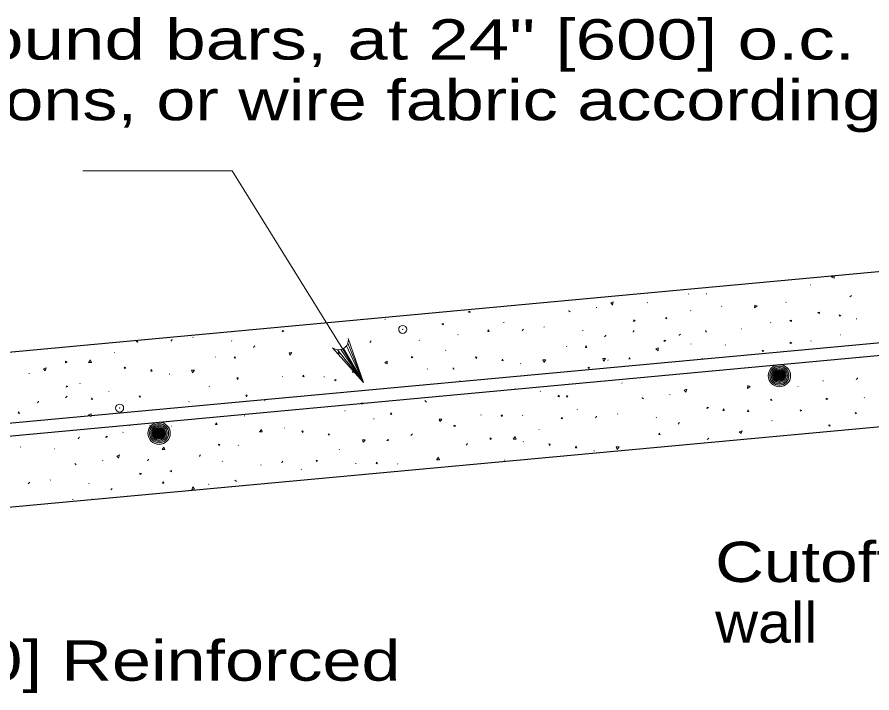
# Model space of a CAD drawing. Extents: x 1083.1 to 1117.1, y 697.4 to 741.4.
# Drawn here: x 1105.172 to 1108.478, y 723.186 to 725.801 of the extents above; entities that cross this region are included whole.
import ezdxf

# ---------------------------------------------------------------- set-up
doc = ezdxf.new("R2010")
doc.units = 0
doc.header["$LTSCALE"] = 0.062
doc.header["$PDMODE"] = 32
doc.header["$PDSIZE"] = 0.031
doc.layers.add('1', color=7, linetype='Continuous', lineweight=13)

msp = doc.modelspace()

# ---------------------------------------------------------------- hatches: boundary and pattern name
at = {"layer": '1'}
h = msp.add_hatch(color=256, dxfattribs=at)
edge = h.paths.add_edge_path()
edge.add_ellipse((1108.12022, 724.41349), major_axis=(0.04324, 0), ratio=0.9998948, start_angle=0, end_angle=360)
h = msp.add_hatch(color=256, dxfattribs=at)
edge = h.paths.add_edge_path()
edge.add_ellipse((1108.12004, 724.41361), major_axis=(0.03676, 0), ratio=0.9998948, start_angle=0, end_angle=360)
h = msp.add_hatch(color=256, dxfattribs=at)
edge = h.paths.add_edge_path()
edge.add_ellipse((1108.11984, 724.41371), major_axis=(0.03124, 0), ratio=0.9998948, start_angle=0, end_angle=360)
h = msp.add_hatch(color=256, dxfattribs=at)
edge = h.paths.add_edge_path()
edge.add_ellipse((1108.11972, 724.4138), major_axis=(0.02656, 0), ratio=0.9998948, start_angle=0, end_angle=360)
h = msp.add_hatch(color=256, dxfattribs=at)
edge = h.paths.add_edge_path()
edge.add_ellipse((1108.11957, 724.41387), major_axis=(0.02257, 0), ratio=0.9998948, start_angle=0, end_angle=360)
h = msp.add_hatch(color=256, dxfattribs=at)
edge = h.paths.add_edge_path()
edge.add_ellipse((1108.11941, 724.41393), major_axis=(0.01919, 0), ratio=0.9998948, start_angle=0, end_angle=360)
h = msp.add_hatch(color=256, dxfattribs=at)
edge = h.paths.add_edge_path()
edge.add_ellipse((1108.11928, 724.41399), major_axis=(0.01631, 0), ratio=0.9998948, start_angle=0, end_angle=360)
h = msp.add_hatch(color=256, dxfattribs=at)
edge = h.paths.add_edge_path()
edge.add_ellipse((1108.11912, 724.41403), major_axis=(0.01386, 0), ratio=0.9998948, start_angle=0, end_angle=360)
h = msp.add_hatch(color=256, dxfattribs=at)
edge = h.paths.add_edge_path()
edge.add_ellipse((1108.11898, 724.41407), major_axis=(0.01178, 0), ratio=0.9998948, start_angle=0, end_angle=360)
h = msp.add_hatch(color=256, dxfattribs=at)
edge = h.paths.add_edge_path()
edge.add_ellipse((1108.11882, 724.4141), major_axis=(0.01002, 0), ratio=0.9998948, start_angle=0, end_angle=360)
h = msp.add_hatch(color=256, dxfattribs=at)
edge = h.paths.add_edge_path()
edge.add_ellipse((1108.11869, 724.41413), major_axis=(0.00851, 0), ratio=0.9998948, start_angle=0, end_angle=360)
h = msp.add_hatch(color=256, dxfattribs=at)
edge = h.paths.add_edge_path()
edge.add_ellipse((1108.11857, 724.4142), major_axis=(0.00724, 0), ratio=0.9998948, start_angle=0, end_angle=360)
h = msp.add_hatch(color=256, dxfattribs=at)
edge = h.paths.add_edge_path()
edge.add_ellipse((1108.11847, 724.41426), major_axis=(0.00615, 0), ratio=0.9998948, start_angle=0, end_angle=360)
h = msp.add_hatch(color=256, dxfattribs=at)
edge = h.paths.add_edge_path()
edge.add_ellipse((1108.11835, 724.41431), major_axis=(0.00523, 0), ratio=0.9998948, start_angle=0, end_angle=360)
h = msp.add_hatch(color=256, dxfattribs=at)
edge = h.paths.add_edge_path()
edge.add_ellipse((1108.11824, 724.41435), major_axis=(0.00444, 0), ratio=0.9998948, start_angle=0, end_angle=360)
h = msp.add_hatch(color=256, dxfattribs=at)
edge = h.paths.add_edge_path()
edge.add_ellipse((1108.11835, 724.41434), major_axis=(0.00378, 0), ratio=0.9998948, start_angle=0, end_angle=360)
h = msp.add_hatch(color=256, dxfattribs=at)
edge = h.paths.add_edge_path()
edge.add_ellipse((1108.11845, 724.41433), major_axis=(0.00321, 0), ratio=0.9998948, start_angle=0, end_angle=360)
h = msp.add_hatch(color=256, dxfattribs=at)
edge = h.paths.add_edge_path()
edge.add_ellipse((1108.11854, 724.41433), major_axis=(0.00273, 0), ratio=0.9998948, start_angle=0, end_angle=360)
h = msp.add_hatch(color=256, dxfattribs=at)
edge = h.paths.add_edge_path()
edge.add_ellipse((1108.11857, 724.41432), major_axis=(0.00232, 0), ratio=0.9998948, start_angle=0, end_angle=360)
h = msp.add_hatch(color=256, dxfattribs=at)
edge = h.paths.add_edge_path()
edge.add_ellipse((1108.11856, 724.41436), major_axis=(0.00197, 0), ratio=0.9998948, start_angle=0, end_angle=360)
h = msp.add_hatch(color=256, dxfattribs=at)
edge = h.paths.add_edge_path()
edge.add_ellipse((1108.11872, 724.41435), major_axis=(0.00168, 0), ratio=0.9998948, start_angle=0, end_angle=360)
h = msp.add_hatch(color=256, dxfattribs=at)
edge = h.paths.add_edge_path()
edge.add_ellipse((1105.72135, 724.19072), major_axis=(0.04324, 0), ratio=0.9998948, start_angle=0, end_angle=360)
h = msp.add_hatch(color=256, dxfattribs=at)
edge = h.paths.add_edge_path()
edge.add_ellipse((1105.72121, 724.19093), major_axis=(0.03676, 0), ratio=0.9998948, start_angle=0, end_angle=360)
h = msp.add_hatch(color=256, dxfattribs=at)
edge = h.paths.add_edge_path()
edge.add_ellipse((1105.7211, 724.19111), major_axis=(0.03124, 0), ratio=0.9998948, start_angle=0, end_angle=360)
h = msp.add_hatch(color=256, dxfattribs=at)
edge = h.paths.add_edge_path()
edge.add_ellipse((1105.721, 724.19126), major_axis=(0.02656, 0), ratio=0.9998948, start_angle=0, end_angle=360)
h = msp.add_hatch(color=256, dxfattribs=at)
edge = h.paths.add_edge_path()
edge.add_ellipse((1105.72092, 724.19139), major_axis=(0.02257, 0), ratio=0.9998948, start_angle=0, end_angle=360)
h = msp.add_hatch(color=256, dxfattribs=at)
edge = h.paths.add_edge_path()
edge.add_ellipse((1105.72085, 724.1915), major_axis=(0.01919, 0), ratio=0.9998948, start_angle=0, end_angle=360)
h = msp.add_hatch(color=256, dxfattribs=at)
edge = h.paths.add_edge_path()
edge.add_ellipse((1105.72079, 724.19159), major_axis=(0.01631, 0), ratio=0.9998948, start_angle=0, end_angle=360)
h = msp.add_hatch(color=256, dxfattribs=at)
edge = h.paths.add_edge_path()
edge.add_ellipse((1105.72074, 724.19167), major_axis=(0.01386, 0), ratio=0.9998948, start_angle=0, end_angle=360)
h = msp.add_hatch(color=256, dxfattribs=at)
edge = h.paths.add_edge_path()
edge.add_ellipse((1105.72069, 724.19173), major_axis=(0.01178, 0), ratio=0.9998948, start_angle=0, end_angle=360)
h = msp.add_hatch(color=256, dxfattribs=at)
edge = h.paths.add_edge_path()
edge.add_ellipse((1105.72066, 724.19179), major_axis=(0.01002, 0), ratio=0.9998948, start_angle=0, end_angle=360)
h = msp.add_hatch(color=256, dxfattribs=at)
edge = h.paths.add_edge_path()
edge.add_ellipse((1105.72062, 724.19184), major_axis=(0.00851, 0), ratio=0.9998948, start_angle=0, end_angle=360)
h = msp.add_hatch(color=256, dxfattribs=at)
edge = h.paths.add_edge_path()
edge.add_ellipse((1105.7206, 724.19188), major_axis=(0.00724, 0), ratio=0.9998948, start_angle=0, end_angle=360)
h = msp.add_hatch(color=256, dxfattribs=at)
edge = h.paths.add_edge_path()
edge.add_ellipse((1105.72058, 724.19192), major_axis=(0.00615, 0), ratio=0.9998948, start_angle=0, end_angle=360)
h = msp.add_hatch(color=256, dxfattribs=at)
edge = h.paths.add_edge_path()
edge.add_ellipse((1105.72056, 724.19195), major_axis=(0.00523, 0), ratio=0.9998948, start_angle=0, end_angle=360)
h = msp.add_hatch(color=256, dxfattribs=at)
edge = h.paths.add_edge_path()
edge.add_ellipse((1105.72054, 724.19197), major_axis=(0.00444, 0), ratio=0.9998948, start_angle=0, end_angle=360)
h = msp.add_hatch(color=256, dxfattribs=at)
edge = h.paths.add_edge_path()
edge.add_ellipse((1105.72053, 724.19199), major_axis=(0.00378, 0), ratio=0.9998948, start_angle=0, end_angle=360)
h = msp.add_hatch(color=256, dxfattribs=at)
edge = h.paths.add_edge_path()
edge.add_ellipse((1105.72051, 724.19201), major_axis=(0.00321, 0), ratio=0.9998948, start_angle=0, end_angle=360)

# ---------------------------------------------------------------- linework, layer by layer
for p, q in [((1105.42633, 725.20642), (1106.00458, 725.20642)), ((1106.51225, 724.38708), (1106.00458, 725.20642)), ((1108.32183, 724.79408), (1108.32808, 724.79883)), ((1108.241, 724.7655), (1108.239, 724.76475)), ((1107.76858, 724.72933), (1107.77058, 724.73)), ((1107.83717, 724.7295), (1107.83917, 724.73017)), ((1107.60925, 724.69483), (1107.61008, 724.69675)), ((1108.14667, 724.69775), (1108.1455, 724.69617)), ((1107.41175, 724.67742), (1107.41375, 724.67675)), ((1107.7775, 724.66392), (1107.77675, 724.66592)), ((1107.898, 724.68267), (1107.89683, 724.68117)), ((1106.595, 724.631), (1106.597, 724.63175)), ((1108.41917, 724.63408), (1108.41717, 724.63333)), ((1107.05375, 724.61867), (1107.05525, 724.61983)), ((1107.20992, 724.6015), (1107.21142, 724.60267)), ((1107.97225, 724.59442), (1107.97425, 724.59508)), ((1108.08575, 724.618), (1108.08775, 724.61867)), ((1105.85167, 724.56108), (1105.85317, 724.56233)), ((1106.8785, 724.57292), (1106.8765, 724.57217)), ((1107.36058, 724.58958), (1107.35975, 724.58758)), ((1108.35683, 724.57183), (1108.35492, 724.571)), ((1106.00233, 724.54925), (1106.0015, 724.54725)), ((1106.44558, 724.52883), (1106.51225, 724.38708)), ((1106.45142, 724.53942), (1106.51225, 724.38708)), ((1106.72717, 724.55025), (1106.72908, 724.551)), ((1107.29817, 724.52725), (1107.2975, 724.52533)), ((1107.77867, 724.53492), (1107.7795, 724.53692)), ((1107.90992, 724.532), (1107.91192, 724.53283)), ((1108.24333, 724.54825), (1108.24133, 724.54742)), ((1105.54933, 724.50333), (1105.54867, 724.50133)), ((1106.41167, 724.51383), (1106.51225, 724.38708)), ((1106.424, 724.51475), (1106.51225, 724.38708)), ((1106.43458, 724.51908), (1106.51225, 724.38708)), ((1106.8305, 724.51192), (1106.82933, 724.51042)), ((1105.93992, 724.48683), (1105.93925, 724.48483)), ((1107.12017, 724.46067), (1107.11942, 724.45875)), ((1107.45767, 724.47475), (1107.45683, 724.47283)), ((1107.82208, 724.48083), (1107.82283, 724.47883)), ((1108.43108, 724.48342), (1108.43225, 724.48492)), ((1106.75775, 724.439), (1106.75967, 724.43967)), ((1105.21808, 724.4225), (1105.22008, 724.42175)), ((1105.76192, 724.42025), (1105.76117, 724.41825)), ((1106.19892, 724.41208), (1106.19825, 724.41008)), ((1106.36025, 724.41025), (1106.35958, 724.40825)), ((1106.88492, 724.39242), (1106.88567, 724.39442)), ((1107.44725, 724.39392), (1107.4465, 724.39192)), ((1108.29025, 724.39383), (1108.28833, 724.393)), ((1105.41542, 724.38258), (1105.41617, 724.38458)), ((1105.91633, 724.37333), (1105.91567, 724.37142)), ((1107.0985, 724.36342), (1107.09767, 724.36142)), ((1107.5125, 724.385), (1107.5105, 724.38567)), ((1108.193, 724.372), (1108.191, 724.37133)), ((1105.52675, 724.352), (1105.52742, 724.35392)), ((1106.39892, 724.34192), (1106.39883, 724.34192)), ((1106.92708, 724.32875), (1106.92717, 724.32867)), ((1107.19483, 724.35283), (1107.19642, 724.354)), ((1107.69575, 724.34042), (1107.69775, 724.33967)), ((1108.44825, 724.32725), (1108.4495, 724.32883)), ((1105.83667, 724.31242), (1105.83817, 724.31367)), ((1106.13117, 724.31783), (1106.12958, 724.31667)), ((1106.44108, 724.27825), (1106.44033, 724.27625)), ((1106.96575, 724.26042), (1106.9665, 724.26242)), ((1107.12708, 724.25858), (1107.12792, 724.26058)), ((1107.33758, 724.28167), (1107.33908, 724.28283)), ((1107.49383, 724.2645), (1107.49533, 724.26567)), ((1106.05142, 724.25692), (1106.05208, 724.25892)), ((1106.55233, 724.24758), (1106.55167, 724.24567)), ((1107.64442, 724.25258), (1107.64375, 724.25058)), ((1108.08992, 724.23925), (1108.09192, 724.24008)), ((1105.58233, 724.19525), (1105.58075, 724.194)), ((1105.6075, 724.21992), (1105.60817, 724.22192)), ((1105.76883, 724.21817), (1105.76967, 724.22017)), ((1106.20583, 724.20992), (1106.20658, 724.21192)), ((1107.19158, 724.20683), (1107.19075, 724.20483)), ((1108.15833, 724.20075), (1108.15817, 724.20075)), ((1105.18492, 724.13883), (1105.18408, 724.13683)), ((1105.31883, 724.13008), (1105.31683, 724.13075)), ((1106.02783, 724.14333), (1106.02858, 724.14533)), ((1106.41842, 724.12683), (1106.41908, 724.12883)), ((1107.13058, 724.15883), (1107.12908, 724.15767)), ((1107.40408, 724.12367), (1107.40333, 724.12175)), ((1105.50208, 724.0855), (1105.50392, 724.08467)), ((1105.9655, 724.08108), (1105.96625, 724.08308)), ((1106.11608, 724.06908), (1106.11467, 724.068)), ((1106.48275, 724.075), (1106.48208, 724.07308)), ((1106.64425, 724.07325), (1106.64342, 724.07125)), ((1107.0575, 724.08608), (1107.05833, 724.088)), ((1106.27225, 724.05192), (1106.27075, 724.05083)), ((1105.30017, 724.0095), (1105.30167, 724.01075)), ((1105.45075, 723.99758), (1105.45, 723.99567)), ((1105.91425, 723.99325), (1105.91225, 723.99392)), ((1105.38842, 723.93525), (1105.38767, 723.93333)), ((1105.46217, 723.93675), (1105.461, 723.93333)), ((1105.46383, 723.93367), (1105.46217, 723.93675))]:
    msp.add_line(p, q, dxfattribs=at)
at = {"layer": '1', "lineweight": 25}
for p, q in [((1110.5145, 724.72675), (1103.31092, 724.05875)), ((1110.51908, 724.67717), (1103.29317, 724.007)), ((1110.14883, 724.368), (1103.29017, 723.73208))]:
    msp.add_line(p, q, dxfattribs=at)
msp.add_lwpolyline([(1110.14883, 724.96767), (1107.49917, 724.722), (1103.29017, 724.33175)], dxfattribs=at)
at = {"layer": '1'}
for points in [[(1108.33158, 724.79917), (1108.33142, 724.79058), (1108.322, 724.794)], [(1108.3985, 724.7235), (1108.39792, 724.72208), (1108.393, 724.71792)], [(1107.4745, 724.68692), (1107.478, 724.69875), (1107.46783, 724.69483), (1107.47433, 724.68717)], [(1107.3055, 724.66625), (1107.30608, 724.66483), (1107.31108, 724.66067)], [(1108.0345, 724.68342), (1108.02458, 724.676), (1108.02475, 724.68692), (1108.03425, 724.6835)], [(1107.131, 724.59308), (1107.12958, 724.5925), (1107.12542, 724.5875)], [(1107.44992, 724.56892), (1107.4485, 724.56833), (1107.44442, 724.56342)], [(1107.5535, 724.583), (1107.55475, 724.58358), (1107.559, 724.58858)], [(1107.73233, 724.569), (1107.73292, 724.57042), (1107.73792, 724.57458)], [(1107.83325, 724.58708), (1107.83467, 724.5865), (1107.83883, 724.5815)], [(1105.63575, 724.54925), (1105.63408, 724.54442), (1105.63942, 724.54358), (1105.6365, 724.54933)], [(1105.77275, 724.55258), (1105.77133, 724.552), (1105.76708, 724.547)], [(1106.09167, 724.5285), (1106.09033, 724.52792), (1106.08617, 724.52292)], [(1106.453, 724.55758), (1106.51225, 724.38708), (1106.392, 724.52167)], [(1106.5365, 724.54233), (1106.53708, 724.54375), (1106.54208, 724.54792)], [(1105.23158, 724.51175), (1105.23158, 724.51167), (1105.23192, 724.51175)], [(1106.2275, 724.49283), (1106.23492, 724.50267), (1106.224, 724.5025), (1106.22742, 724.49308)], [(1107.64225, 724.51742), (1107.652, 724.51), (1107.65192, 724.52092), (1107.64242, 724.5175)], [(1105.45633, 724.47433), (1105.449, 724.46458), (1105.45983, 724.46475), (1105.4565, 724.47417)], [(1106.59417, 724.46283), (1106.604, 724.47025), (1106.60383, 724.45925), (1106.59433, 724.46275)], [(1107.20917, 724.46517), (1107.21658, 724.47492), (1107.20567, 724.47475), (1107.20908, 724.46533)], [(1107.44067, 724.46992), (1107.448, 724.47975), (1107.437, 724.47958), (1107.4405, 724.47008)], [(1105.28075, 724.432), (1105.28433, 724.44375), (1105.27417, 724.43983), (1105.28067, 724.43217)], [(1105.85092, 724.42467), (1105.85842, 724.4345), (1105.84742, 724.43442), (1105.85075, 724.42492)], [(1106.47542, 724.43717), (1106.46792, 724.42742), (1106.47892, 724.42758), (1106.47542, 724.437)], [(1106.86292, 724.43817), (1106.8615, 724.43875), (1106.85742, 724.44375)], [(1106.49775, 724.42108), (1106.49633, 724.4205), (1106.49217, 724.4155)], [(1108.42267, 724.40458), (1108.42208, 724.40317), (1108.41708, 724.399)], [(1107.75842, 724.34992), (1107.762, 724.36175), (1107.75167, 724.35775), (1107.75817, 724.35017)], [(1108.00733, 724.37208), (1107.9975, 724.36458), (1107.99767, 724.37558), (1108.00717, 724.37225)], [(1105.35975, 724.328), (1105.36108, 724.32867), (1105.36533, 724.33367)], [(1107.58933, 724.32925), (1107.59, 724.32783), (1107.595, 724.32367)], [(1105.25625, 724.31392), (1105.25483, 724.31333), (1105.25067, 724.30842)], [(1106.74933, 724.31717), (1106.75, 724.31575), (1106.755, 724.31158)], [(1105.44858, 724.2625), (1105.45833, 724.25508), (1105.45817, 724.266), (1105.44875, 724.26258)], [(1106.80775, 724.23575), (1106.81525, 724.24558), (1106.80425, 724.24542), (1106.80767, 724.236)], [(1107.41483, 724.25608), (1107.41342, 724.2555), (1107.40933, 724.2505)], [(1107.73392, 724.23192), (1107.7325, 724.23133), (1107.72833, 724.22642)], [(1106.11683, 724.2055), (1106.1095, 724.19575), (1106.12033, 724.19592), (1106.117, 724.20533)], [(1107.965, 724.1965), (1107.97675, 724.2), (1107.97275, 724.18983), (1107.96517, 724.19633)], [(1105.41375, 724.17525), (1105.41242, 724.17458), (1105.40817, 724.16967)], [(1106.51133, 724.15583), (1106.51883, 724.16567), (1106.50792, 724.1655), (1106.51125, 724.156)], [(1106.70117, 724.18833), (1106.69975, 724.18775), (1106.69558, 724.18275)], [(1107.0985, 724.17783), (1107.09108, 724.16792), (1107.10208, 724.16817), (1107.09858, 724.17758)], [(1107.84692, 724.17192), (1107.84633, 724.1705), (1107.84142, 724.16642)], [(1105.74025, 724.13733), (1105.73283, 724.12758), (1105.74383, 724.12775), (1105.74033, 724.13717)], [(1106.90867, 724.14533), (1106.91008, 724.14592), (1106.91425, 724.15092)], [(1107.493, 724.12817), (1107.5005, 724.13792), (1107.4895, 724.13775), (1107.493, 724.12833)], [(1105.56475, 724.095), (1105.56833, 724.10675), (1105.558, 724.10283), (1105.5645, 724.09517)], [(1105.87608, 724.10167), (1105.8775, 724.10225), (1105.88167, 724.10725)], [(1106.80217, 724.09783), (1106.79475, 724.08808), (1106.80575, 724.08825), (1106.80225, 724.09767)], [(1105.39567, 724.07425), (1105.39633, 724.07292), (1105.40133, 724.06867)], [(1105.68233, 724.08933), (1105.681, 724.08892), (1105.67675, 724.08392)], [(1106.195, 724.07758), (1106.19642, 724.07817), (1106.20058, 724.08317)], [(1105.22117, 724.00117), (1105.21975, 724.0005), (1105.21558, 723.9955)], [(1106.0205, 724.00442), (1106.01992, 724.00583), (1106.01492, 724.01)], [(1105.54017, 723.97692), (1105.53883, 723.97633), (1105.53467, 723.97142)], [(1105.85158, 723.98375), (1105.848, 723.97192), (1105.85817, 723.97583), (1105.85167, 723.9835)]]:
    msp.add_lwpolyline(points, dxfattribs=at)
for points in [[(1106.92508, 724.65958), (1106.9195, 724.65767), (1106.91875, 724.66283)], [(1108.26925, 724.65742), (1108.27483, 724.65942), (1108.27567, 724.65417)], [(1107.56267, 724.627), (1107.55708, 724.629), (1107.55625, 724.62367)], [(1107.67817, 724.63625), (1107.68367, 724.63825), (1107.68442, 724.633)], [(1108.16117, 724.62658), (1108.16683, 724.62858), (1108.1675, 724.62325)], [(1108.35833, 724.64558), (1108.35275, 724.64358), (1108.352, 724.64883)], [(1106.81483, 724.61367), (1106.82033, 724.61567), (1106.82117, 724.61033)], [(1106.20442, 724.58658), (1106.19883, 724.58858), (1106.198, 724.58325)], [(1106.99433, 724.59042), (1106.99233, 724.58475), (1106.99767, 724.58408)], [(1107.372, 724.52875), (1107.37008, 724.52317), (1107.37533, 724.52242)], [(1107.68058, 724.54933), (1107.675, 724.55133), (1107.67433, 724.546)], [(1108.16792, 724.5395), (1108.16233, 724.53758), (1108.16158, 724.54292)], [(1106.41425, 724.50267), (1106.41225, 724.497), (1106.41758, 724.49625)], [(1108.05983, 724.50875), (1108.05425, 724.50675), (1108.05342, 724.512)], [(1105.36542, 724.46717), (1105.35983, 724.46908), (1105.35908, 724.46383)], [(1106.01375, 724.48833), (1106.01183, 724.48275), (1106.01708, 724.48192)], [(1106.70317, 724.48442), (1106.69758, 724.48258), (1106.69692, 724.48775)], [(1106.94833, 724.48008), (1106.95033, 724.48567), (1106.94508, 724.48642)], [(1107.04933, 724.47742), (1107.04733, 724.47183), (1107.05258, 724.47108)], [(1107.54017, 724.48442), (1107.53833, 724.47883), (1107.54358, 724.47808)], [(1105.59008, 724.43967), (1105.59208, 724.44525), (1105.58683, 724.446)], [(1105.69108, 724.437), (1105.68908, 724.43142), (1105.69433, 724.43067)], [(1107.38383, 724.43967), (1107.38583, 724.44525), (1107.38058, 724.44608)], [(1106.02558, 724.39933), (1106.02758, 724.40492), (1106.02242, 724.40558)], [(1106.27892, 724.41575), (1106.27692, 724.41025), (1106.28217, 724.4095)], [(1106.39892, 724.39592), (1106.4045, 724.39392), (1106.40517, 724.39917)], [(1105.369, 724.372), (1105.36342, 724.374), (1105.36258, 724.36875)], [(1105.461, 724.328), (1105.459, 724.32242), (1105.46425, 724.32175)], [(1105.64675, 724.33692), (1105.64492, 724.33133), (1105.65008, 724.3305)], [(1106.06, 724.33233), (1106.062, 724.33783), (1106.05667, 724.33867)], [(1107.266, 724.33833), (1107.264, 724.33275), (1107.26933, 724.332)], [(1107.2985, 724.3375), (1107.2965, 724.332), (1107.30183, 724.33125)], [(1106.50675, 724.30217), (1106.50875, 724.30775), (1106.50358, 724.30842)], [(1108.08433, 724.32075), (1108.08992, 724.32267), (1108.09075, 724.31742)], [(1108.307, 724.32283), (1108.30142, 724.32083), (1108.30067, 724.32617)], [(1105.17833, 724.27375), (1105.17642, 724.26817), (1105.18158, 724.2675)], [(1106.61775, 724.26983), (1106.61583, 724.26425), (1106.62117, 724.2635)], [(1107.04708, 724.25475), (1107.04908, 724.26042), (1107.04383, 724.26117)], [(1107.84658, 724.28992), (1107.84092, 724.292), (1107.84025, 724.28667)], [(1107.905, 724.28467), (1107.907, 724.27908), (1107.90175, 724.27825)], [(1108.00008, 724.28117), (1108.00208, 724.27558), (1107.99675, 724.27483)], [(1108.20692, 724.27867), (1108.20125, 724.27667), (1108.20058, 724.282)], [(1108.42, 724.26792), (1108.41442, 724.266), (1108.41367, 724.27117)], [(1105.94217, 724.23092), (1105.94017, 724.22533), (1105.94542, 724.22458)], [(1107.27825, 724.25342), (1107.27625, 724.24775), (1107.2815, 724.24708)], [(1105.68883, 724.21442), (1105.69083, 724.22), (1105.68558, 724.22067)], [(1106.27675, 724.19325), (1106.27867, 724.19883), (1106.2735, 724.19958)], [(1106.86025, 724.21833), (1106.86583, 724.21633), (1106.86658, 724.22158)], [(1108.30967, 724.222), (1108.31525, 724.22392), (1108.316, 724.21867)], [(1105.52175, 724.17792), (1105.51617, 724.17992), (1105.51542, 724.17458)], [(1106.37767, 724.1905), (1106.37567, 724.185), (1106.38092, 724.18425)], [(1106.60233, 724.16317), (1106.60792, 724.16117), (1106.60867, 724.16642)], [(1107.0075, 724.1705), (1107.00192, 724.1725), (1107.00125, 724.16725)], [(1107.65592, 724.19175), (1107.65392, 724.18608), (1107.65925, 724.18542)], [(1105.954, 724.14192), (1105.95592, 724.14742), (1105.95075, 724.14825)], [(1107.23233, 724.14308), (1107.23425, 724.14867), (1107.22892, 724.14942)], [(1107.33317, 724.14042), (1107.33117, 724.13483), (1107.3365, 724.13408)], [(1106.33167, 724.08025), (1106.33367, 724.08592), (1106.3285, 724.08658)], [(1106.56275, 724.07875), (1106.56083, 724.07325), (1106.56617, 724.0725)], [(1105.65292, 724.035), (1105.64725, 724.037), (1105.6465, 724.03175)], [(1105.76333, 724.04367), (1105.76892, 724.04167), (1105.76975, 724.04692)], [(1105.73742, 724.00367), (1105.73933, 723.998), (1105.73417, 723.99733)]]:
    msp.add_lwpolyline(points, close=True, dxfattribs=at)
msp.add_arc((1106.4152, 724.55193), 0.0382, 232.54301, 8.36914, dxfattribs=at)
for centre, major_axis in [((1108.12022, 724.41349), (0.04324, 0)), ((1108.12004, 724.41361), (0.03676, 0)), ((1108.11984, 724.41371), (0.03124, 0)), ((1108.11972, 724.4138), (0.02656, 0)), ((1108.11957, 724.41387), (0.02257, 0)), ((1108.11941, 724.41393), (0.01919, 0)), ((1108.11928, 724.41399), (0.01631, 0)), ((1108.11912, 724.41403), (0.01386, 0)), ((1108.11898, 724.41407), (0.01178, 0)), ((1108.11882, 724.4141), (0.01002, 0)), ((1108.11869, 724.41413), (0.00851, 0)), ((1108.11857, 724.4142), (0.00724, 0)), ((1108.11847, 724.41426), (0.00615, 0)), ((1108.11835, 724.41431), (0.00523, 0)), ((1108.11824, 724.41435), (0.00444, 0)), ((1108.11835, 724.41434), (0.00378, 0)), ((1108.11845, 724.41433), (0.00321, 0)), ((1108.11854, 724.41433), (0.00273, 0)), ((1108.11857, 724.41432), (0.00232, 0)), ((1108.11856, 724.41436), (0.00197, 0)), ((1108.11872, 724.41435), (0.00168, 0)), ((1105.72135, 724.19072), (0.04324, 0)), ((1105.72121, 724.19093), (0.03676, 0)), ((1105.7211, 724.19111), (0.03124, 0)), ((1105.721, 724.19126), (0.02656, 0)), ((1105.72092, 724.19139), (0.02257, 0)), ((1105.72085, 724.1915), (0.01919, 0)), ((1105.72079, 724.19159), (0.01631, 0)), ((1105.72074, 724.19167), (0.01386, 0)), ((1105.72069, 724.19173), (0.01178, 0)), ((1105.72066, 724.19179), (0.01002, 0)), ((1105.72062, 724.19184), (0.00851, 0)), ((1105.7206, 724.19188), (0.00724, 0)), ((1105.72058, 724.19192), (0.00615, 0)), ((1105.72056, 724.19195), (0.00523, 0)), ((1105.72054, 724.19197), (0.00444, 0)), ((1105.72053, 724.19199), (0.00378, 0)), ((1105.72051, 724.19201), (0.00321, 0))]:
    msp.add_ellipse(centre, major_axis=major_axis, ratio=0.999895, dxfattribs=at)
for p in [(1106.66342, 724.59242), (1105.56892, 724.28825)]:
    msp.add_point(p, dxfattribs=at)

# ---------------------------------------------------------------- texts
for s, width, p in [('#3 [#10M] round bars, at 24" [600] o.c.', 1.35, (1103.61583, 725.63633)), ('in two directions, or wire fabric according ', 1.3, (1103.61583, 725.40167)), ('Cutoff', 1.25, (1107.87183, 723.61533)), ('wall', 1.1, (1107.87183, 723.38067)), ('6" [150] Reinforced', 1.3, (1104.3425, 723.2335))]:
    msp.add_text(s, height=0.156, dxfattribs=dict(at, width=width)).set_placement(p)

doc.saveas('drawing.dxf')
